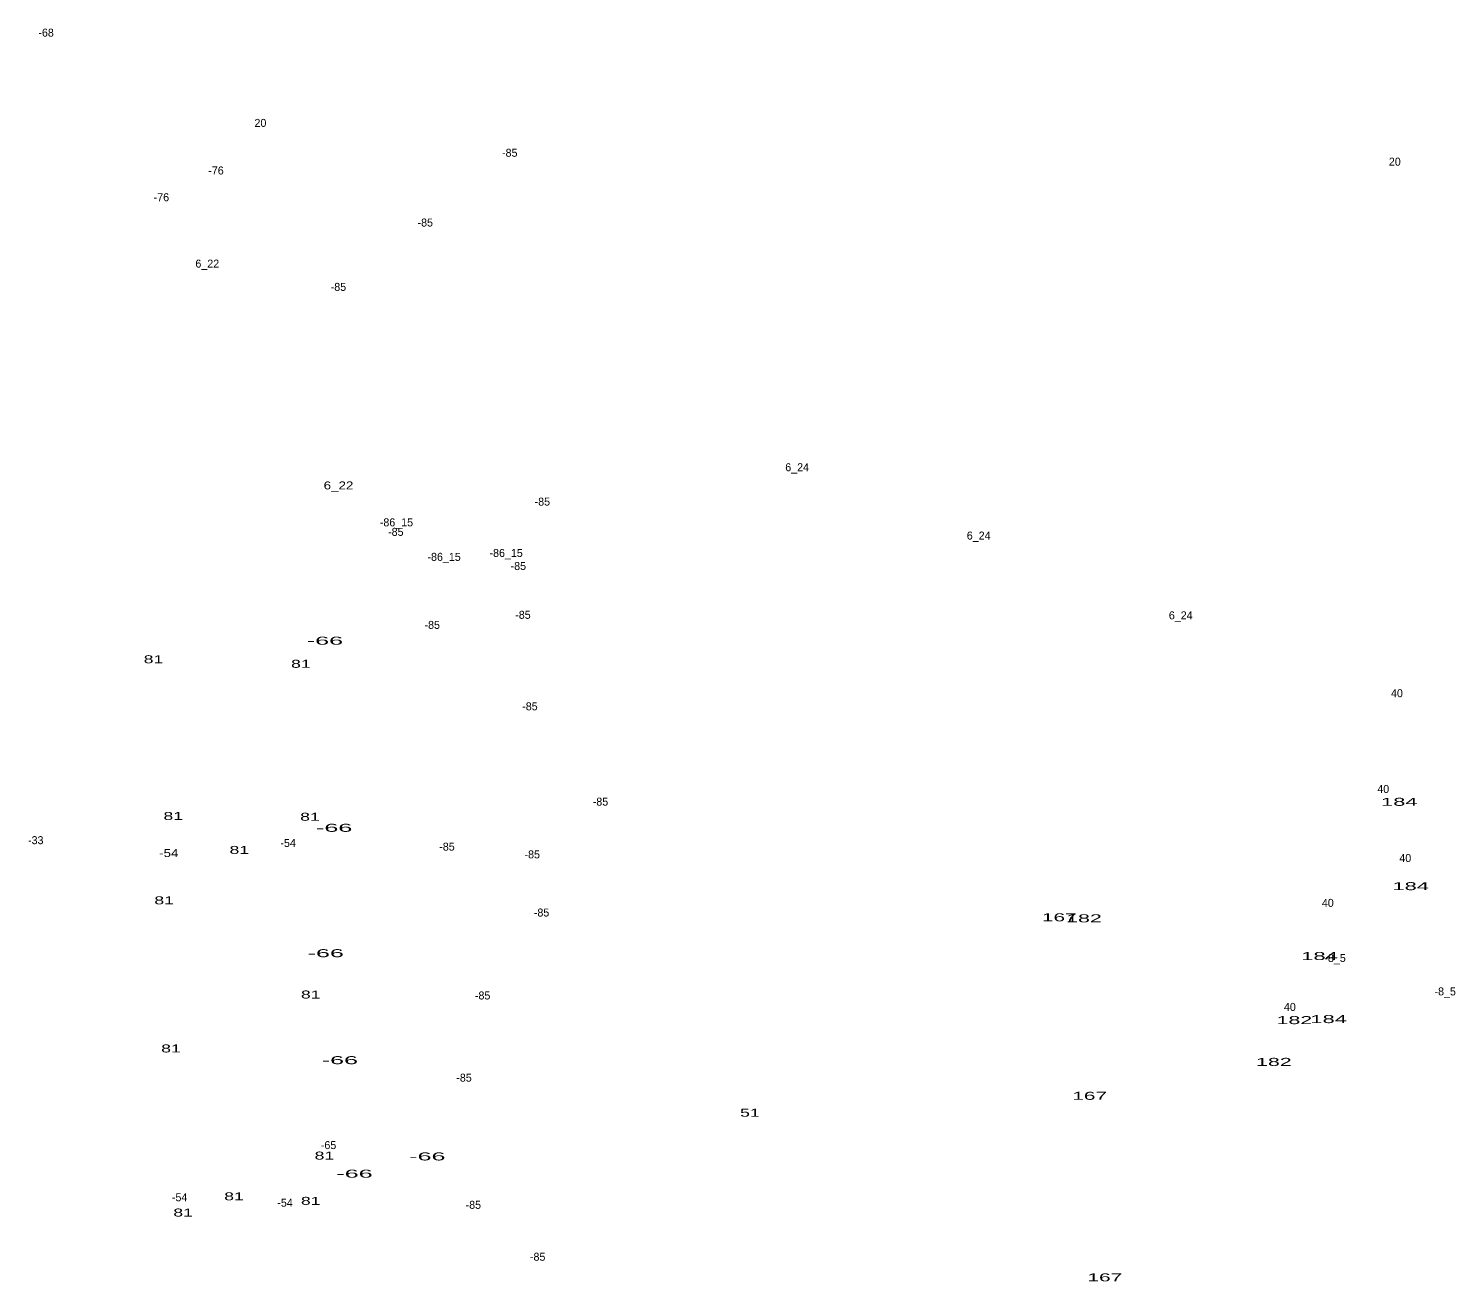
# Model space of a CAD drawing. Extents: x -659624 to -656248, y -1006345 to -1003555.
# Drawn here: x -657718 to -657003, y -1005513 to -1004886 of the extents above; entities that cross this region are included whole.
import ezdxf
from ezdxf.enums import TextEntityAlignment as Align

# ---------------------------------------------------------------- set-up
doc = ezdxf.new("R2010")
doc.units = 0
doc.header["$LTSCALE"] = 1.6
doc.layers.add('24', color=7, linetype='Continuous')

msp = doc.modelspace()

# ---------------------------------------------------------------- texts
at = {"layer": '24'}
for s, p in [('-68', (-657708.91, -1004889.94)), ('20', (-657601.581, -1004935.16)), ('-85', (-657476.735, -1004950.11)), ('20', (-657033.531, -1004954.58)), ('-76', (-657623.825, -1004958.99)), ('-76', (-657651.185, -1004972.39)), ('-85', (-657519.045, -1004985.06)), ('6_22', (-657628.2, -1005005.63)), ('-85', (-657562.525, -1005017.29)), ('6_24', (-657332.814, -1005107.63)), ('-85', (-657460.415, -1005124.86)), ('-86_15', (-657533.472, -1005135.24)), ('-85', (-657533.785, -1005140.01)), ('6_24', (-657241.914, -1005141.87)), ('-86_15', (-657478.542, -1005150.58)), ('-86_15', (-657509.602, -1005152.52)), ('-85', (-657472.445, -1005157.09)), ('-85', (-657515.545, -1005186.61)), ('-85', (-657470.125, -1005181.56)), ('6_24', (-657140.734, -1005181.82)), ('40', (-657032.465, -1005220.83)), ('-85', (-657466.625, -1005227.39)), ('40', (-657039.315, -1005268.78)), ('-85', (-657431.305, -1005275.15)), ('-33', (-657714.075, -1005294.45)), ('-54', (-657587.709, -1005295.85)), ('-85', (-657508.165, -1005297.68)), ('-85', (-657465.465, -1005301.56)), ('40', (-657028.285, -1005303.4)), ('40', (-657067.085, -1005325.85)), ('-85', (-657460.805, -1005330.69)), ('-8_5', (-657063.443, -1005353.46)), ('-85', (-657490.315, -1005372.24)), ('-8_5', (-657008.293, -1005370.2)), ('40', (-657086.095, -1005377.98)), ('-85', (-657499.635, -1005413.41)), ('-65', (-657567.46, -1005447.18)), ('-54', (-657642.049, -1005473.33)), ('-54', (-657589.259, -1005476.04)), ('-85', (-657494.975, -1005477.1)), ('-85', (-657462.755, -1005503.12))]:
    msp.add_text(s, height=4, dxfattribs=at).set_placement(p, align=Align.CENTER)
for s, width, p in [('6_22', 1.25, (-657562.48, -1005116.74)), ('-66', 2.35, (-657569.263, -1005194.52)), ('81', 1.65, (-657655.127, -1005203.82)), ('81', 1.65, (-657581.337, -1005206.1)), ('184', 2.05, (-657031.283, -1005275.24)), ('81', 1.65, (-657645.237, -1005282.34)), ('81', 1.65, (-657576.767, -1005282.72)), ('-66', 2.35, (-657564.653, -1005288.25)), ('-54', 1.25, (-657647.48, -1005300.9)), ('81', 1.65, (-657612.147, -1005299.33)), ('184', 2.05, (-657025.583, -1005317.48)), ('81', 1.65, (-657649.797, -1005324.58)), ('167', 1.95, (-657201.547, -1005333.08)), ('182', 2, (-657189.187, -1005333.59)), ('-66', 2.35, (-657568.873, -1005351.06)), ('184', 2.05, (-657071.223, -1005352.49)), ('81', 1.65, (-657576.387, -1005371.76)), ('182', 2, (-657083.827, -1005384.58)), ('184', 2.05, (-657066.663, -1005384.07)), ('81', 1.65, (-657646.377, -1005398.78)), ('-66', 2.35, (-657561.773, -1005404.65)), ('182', 2, (-657094.097, -1005405.51)), ('167', 1.95, (-657186.327, -1005422.5)), ('51', 1.65, (-657356.497, -1005430.97)), ('81', 1.65, (-657569.547, -1005452.43)), ('-66', 2.35, (-657517.993, -1005452.86)), ('-66', 2.35, (-657554.473, -1005461.5)), ('81', 1.65, (-657614.807, -1005472.84)), ('81', 1.65, (-657576.397, -1005475.12)), ('81', 1.65, (-657640.287, -1005480.97)), ('167', 1.95, (-657178.727, -1005513.44))]:
    msp.add_text(s, height=4, dxfattribs=dict(at, width=width)).set_placement(p, align=Align.CENTER)

doc.saveas('drawing.dxf')
